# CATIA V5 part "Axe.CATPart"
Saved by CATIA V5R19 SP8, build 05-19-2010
Part number: Axe
Publications: "Rayon_axe", "Demilongue_entre_circlips"
Bounding box of the stored display mesh (mm): x -23 to 23, y -12.358 to 12.358, z -12.5 to 12.5
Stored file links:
  F:\! CONCEPTION\PROJET\Mécanisme 544\CAO\Axe.CATPart
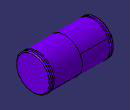
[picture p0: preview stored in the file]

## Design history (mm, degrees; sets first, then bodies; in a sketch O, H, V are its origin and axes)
Parameters
  Rayon_axe = 12.5 mm
  Demilongue_entre_circlips = 20 mm
Body1 (main body)
  Sketch1 on xy-plane, origin (0, 0, 0), H (1, 0, 0), V (0, 1, 0)
    point P1 (-23, 0)
    line L1 (-23, 0) -> (-23, 11.7929)
    line L2 (-23, 11.7929) -> (-22.2929, 12.5)
    line L3 (-22.2929, 12.5) -> (-21, 12.5)
    line L4 (-21, 12.5) -> (-21, 10.5)
    line L5 (-21, 10.5) -> (-20, 10.5)
    line L6 (-20, 10.5) -> (-20, 12.5)
    point P7 (-20, 12.5)
    line L7 (-20, 12.5) -> (0, 12.5)
    point P8 (0, 12.5)
    line L8 (0, 12.5) -> (0, 0)
    line L9 (0, 0) -> (-23, 0)
    distance L7 L9 = 12.5 {= Rayon_axe}
    distance L4 L6 = 1
    distance L5 L7 = 2
    angle L2 L1 = 45
    length L2 = 1
    distance L4 L1 = 2
    distance L6 V = 20 {= Demilongue_entre_circlips}
    coincidence: P1 H, P7 L3, P8 V
    vertical: L1 V, L4 V, L6 V, L8 V
    horizontal: L3 H, L5 H, L7 H, L9 H
  Shaft1: profile Sketch1, axis Sketch1.H, angle 360
  Mirror1: of Shaft1, about yz-plane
